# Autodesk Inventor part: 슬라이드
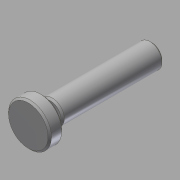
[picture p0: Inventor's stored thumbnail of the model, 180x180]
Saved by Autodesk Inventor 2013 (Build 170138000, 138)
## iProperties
Created: 2015-09
Part Number: 슬라이드
Material: 강철, 연강
Document SubType Name: Modeling
Designer: mduedu
Density: 1 g/cm^3
Author: mduedu
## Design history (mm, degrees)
sketch "스케치1"
  geometry: C1 r 12.5 at (0, 0); 1 further point
  constraints: 1 centre point, 1 coincident
  dimensions: "d0" = 25 diameter of C1
extrude "돌출1" new body sketch "스케치1" distance "d1" = 8; taper "d2" = 0 deg
sketch "스케치2"
  geometry: C1 r 4 at (0, 0); 1 further point
  constraints: 1 centre point, 1 coincident
  dimensions: "d3" = 8 diameter of C1
extrude "돌출2" join sketch "스케치2" distance "d4" = 5; taper "d5" = 0 deg
sketch "스케치3"
  geometry: C1 r 7 at (0, 0); 1 further point
  constraints: 1 centre point, 1 coincident
  dimensions: "d6" = 14 diameter of C1
extrude "돌출3" join sketch "스케치3" distance "d7" = 59; taper "d8" = 0 deg
hole "구멍1" diameter "d11" = 4.134; stored, may be unused: countersink angle "d15" = 90 deg, drill point angle "d17" = 118 deg; dims "d9" = 10, "d10" = 10, "d12" = 9, "d13" = 4, "d14" = 2, "d16" = 12
chamfer "모따기1" distance "d18" = 1; stored, may be unused: second distance "d19" = 2, angle "d20" = 45 deg
node "솔리드1"
